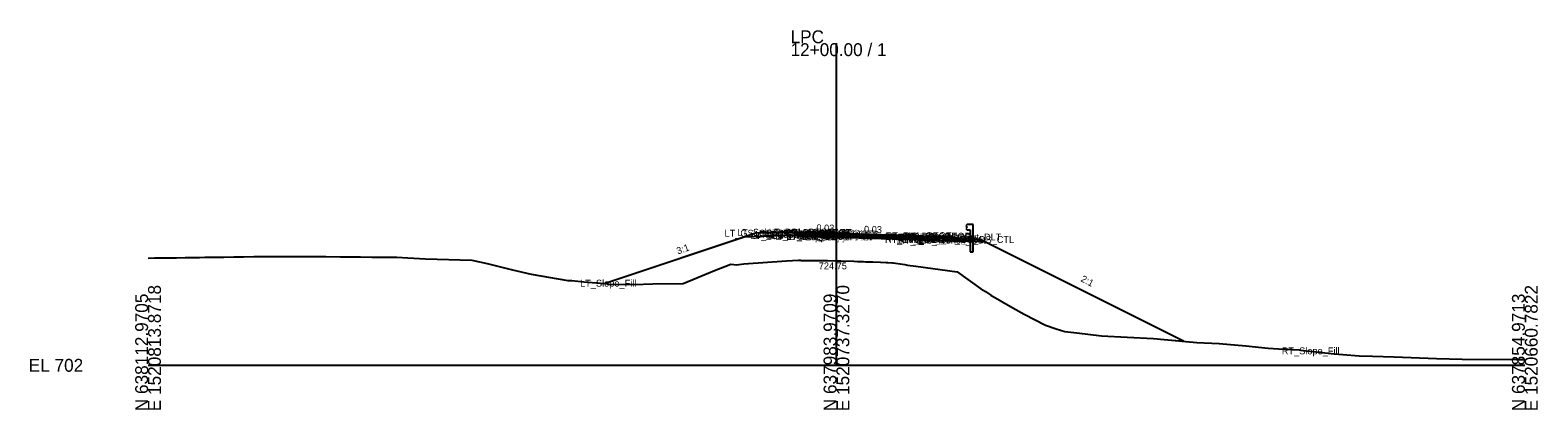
# Model space of a CAD drawing. Extents: x -26 to 303, y -10 to 4521.
# Drawn here: x -25.7 to 302.8, y 1990.3 to 2073 of the extents above; entities that cross this region are included whole.
import ezdxf

# ---------------------------------------------------------------- set-up
doc = ezdxf.new("R2010")
doc.units = 0
for name, color, linetype in [('Default', 7, 'Continuous'), ('Exist Cross Section Cell', 7, 'Continuous'), ('Exist XS Center Line Elevation Label', 7, 'Continuous'), ('Exist XS Ground Line', 7, 'Continuous'), ('Prop CMT Guardrail Graphics', 7, 'Continuous'), ('Prop CMT Pvmt Course 1', 7, 'Continuous'), ('Prop CMT Pvmt Course 2', 7, 'Continuous'), ('Prop CMT Pvmt Course 3', 7, 'Continuous'), ('Prop CMT Pvmt Surface', 7, 'Continuous'), ('Prop CMT Pvmt Surface Shoulder', 7, 'Continuous'), ('Prop CMT Shld Paved Course 1', 7, 'Continuous'), ('Prop CMT Shld Paved Course 2', 7, 'Continuous'), ('Prop CMT Shld Paved Course 3', 7, 'Continuous'), ('Prop CMT Slope Grass', 7, 'Continuous'), ('Prop CMT Subgrade Earthwork', 7, 'Continuous'), ('Prop XS Earthwork Shape', 7, 'Continuous'), ('Prop XS Shear Point Element', 7, 'Continuous')]:
    doc.layers.add(name, color=color, linetype=linetype)

msp = doc.modelspace()

# ---------------------------------------------------------------- linework, layer by layer
at = {"layer": 'Exist Cross Section Cell'}
for p, q in [((150, 2000), (150, 2070.13)), ((0, 2000), (150, 2000)), ((150, 2000), (300, 2000))]:
    msp.add_line(p, q, dxfattribs=at)
at = {"layer": 'Exist XS Ground Line'}
msp.add_lwpolyline([(0, 2023.35), (1.39, 2023.38), (2.09, 2023.39), (3.23, 2023.4), (3.45, 2023.4), (4.21, 2023.41), (5.39, 2023.42), (6.19, 2023.43), (8.08, 2023.46), (9.51, 2023.48), (10.2, 2023.48), (11.24, 2023.5), (12.37, 2023.52), (13.9, 2023.53), (14.95, 2023.55), (15.72, 2023.56), (16.17, 2023.57), (16.54, 2023.57), (18.69, 2023.6), (19.56, 2023.61), (20.81, 2023.63), (23.02, 2023.67), (24.96, 2023.66), (29.32, 2023.66), (30.49, 2023.68), (34.2, 2023.69), (35.79, 2023.68), (38.76, 2023.66), (41.93, 2023.64), (46.28, 2023.6), (48.79, 2023.58), (52.11, 2023.55), (53.38, 2023.54), (54.23, 2023.53), (56.62, 2023.4), (60.46, 2023.17), (70.54, 2022.89), (73.91, 2022.19), (79.44, 2020.82), (83.49, 2019.87), (91.47, 2018.45), (92.35, 2018.46), (94.97, 2018.21), (99.56, 2017.81), (100.45, 2017.67), (105.85, 2017.59), (110.02, 2017.75), (116.63, 2017.82), (123.45, 2020.63), (126.96, 2022.04), (127.62, 2021.92), (128.22, 2021.87), (129.84, 2022.07), (139.12, 2022.72), (141.7, 2022.86), (142.21, 2022.86), (142.26, 2022.85), (142.32, 2022.85), (142.55, 2022.85), (145.11, 2022.83), (145.44, 2022.84), (145.66, 2022.84), (146.76, 2022.82), (148.02, 2022.79), (150, 2022.75), (150.79, 2022.74), (150.91, 2022.74), (150.99, 2022.74), (153.81, 2022.65), (154.57, 2022.62), (155.88, 2022.58), (156.4, 2022.56), (156.72, 2022.55), (157.95, 2022.5), (159.62, 2022.44), (160.87, 2022.41), (161.17, 2022.41), (162.22, 2022.32), (162.33, 2022.31), (162.33, 2022.31), (162.35, 2022.31), (164.87, 2021.92), (165.49, 2021.82), (167.27, 2021.56), (176.3, 2020.33), (181.47, 2016.68), (182.49, 2016.07), (183.61, 2015.29), (188.46, 2012.54), (190.88, 2011.17), (195.58, 2008.71), (197.85, 2007.95), (199.77, 2007.37), (202.35, 2007.04), (207.73, 2006.43), (213.34, 2006.13), (219.08, 2005.84), (221.39, 2005.62), (228.52, 2004.98), (233.39, 2004.72), (239.21, 2004.22), (244.06, 2003.75), (246.34, 2003.61), (250.8, 2003.34), (251.15, 2003.32), (258.44, 2002.52), (260.38, 2002.36), (263.92, 2002.07), (266.79, 2001.98), (271.5, 2001.86), (280.76, 2001.51), (286.37, 2001.32), (298.18, 2001.29), (298.74, 2001.28), (298.83, 2001.28), (300, 2001.27)], dxfattribs=at)
at = {"layer": 'Prop CMT Guardrail Graphics'}
for points in [[(179.78, 2030.68), (178.45, 2030.68), (178.18, 2030.39)], [(178.18, 2030.39), (178.45, 2030.1)], [(179.78, 2024.68), (179.78, 2030.68)], [(178.45, 2030.1), (178.18, 2029.81)], [(178.18, 2029.81), (178.45, 2029.52), (179.12, 2029.52)], [(179.12, 2029.52), (179.12, 2024.68)], [(179.12, 2024.68), (179.78, 2024.68)]]:
    msp.add_lwpolyline(points, dxfattribs=at)
at = {"layer": 'Prop CMT Pvmt Course 1'}
msp.add_line((150.02, 2028.76), (167.01, 2028.23), dxfattribs=at)
for points in [[(150.02, 2028.76), (145.42, 2028.9)], [(145.42, 2028.9), (145.42, 2028.65)], [(145.42, 2028.65), (150.02, 2028.51)], [(150.02, 2028.51), (150.02, 2028.76)], [(150.02, 2028.51), (150.02, 2028.76)], [(167.01, 2027.98), (150.02, 2028.51)], [(167.01, 2028.23), (167.01, 2027.98)]]:
    msp.add_lwpolyline(points, dxfattribs=at)
msp.add_lwpolyline([(150.02, 2028.51), (150.02, 2028.63), (150.02, 2028.63), (150.02, 2028.51)], close=True, dxfattribs=at)
msp.add_lwpolyline([(150.02, 2028.51), (150.02, 2028.63), (150.02, 2028.63), (150.02, 2028.51)], close=True, dxfattribs=at)
at = {"layer": 'Prop CMT Pvmt Course 2'}
for points in [[(150.02, 2028.51), (145.42, 2028.65)], [(145.42, 2028.65), (145.42, 2028.32)], [(145.42, 2028.32), (150.02, 2028.18)], [(150.02, 2028.18), (150.02, 2028.51)], [(150.02, 2028.18), (150.02, 2028.51)], [(150.02, 2028.51), (167.01, 2027.98)], [(167.01, 2027.65), (150.02, 2028.18)], [(167.01, 2027.98), (167.01, 2027.65)]]:
    msp.add_lwpolyline(points, dxfattribs=at)
at = {"layer": 'Prop CMT Pvmt Course 3'}
for points in [[(150.02, 2028.18), (145.42, 2028.32)], [(145.42, 2028.32), (145.42, 2028.07)], [(145.42, 2028.07), (150.02, 2027.93)], [(150.02, 2027.93), (150.02, 2028.18)], [(150.02, 2028.18), (167.01, 2027.65)], [(150.02, 2027.93), (150.02, 2028.18)], [(167.01, 2027.4), (150.02, 2027.93)], [(167.01, 2027.65), (167.01, 2027.4)]]:
    msp.add_lwpolyline(points, dxfattribs=at)
at = {"layer": 'Prop CMT Pvmt Surface'}
for points in [[(150.02, 2028.76), (145.42, 2028.9)], [(150.02, 2028.76), (167.01, 2028.23)]]:
    msp.add_lwpolyline(points, dxfattribs=at)
at = {"layer": 'Prop CMT Pvmt Surface Shoulder'}
for points in [[(145.42, 2028.9), (141.42, 2029.02)], [(167.01, 2028.23), (171.01, 2028.11)]]:
    msp.add_lwpolyline(points, dxfattribs=at)
at = {"layer": 'Prop CMT Shld Paved Course 1'}
for p in [(171.28, 2027.84), (178.18, 2027.65)]:
    msp.add_line(p, (178.18, 2027.39), dxfattribs=at)
for points in [[(145.42, 2028.9), (141.42, 2029.02), (141.17, 2028.78)], [(141.17, 2028.78), (145.42, 2028.65)], [(145.42, 2028.65), (145.42, 2028.9)], [(167.01, 2028.23), (171.01, 2028.11), (171.27, 2027.85)], [(167.01, 2027.98), (167.01, 2028.23)], [(171.27, 2027.85), (167.01, 2027.98)]]:
    msp.add_lwpolyline(points, dxfattribs=at)
at = {"layer": 'Prop CMT Shld Paved Course 2'}
for points in [[(145.42, 2028.65), (141.17, 2028.78), (140.85, 2028.46)], [(140.85, 2028.46), (145.42, 2028.32)], [(145.42, 2028.32), (145.42, 2028.65)], [(167.01, 2027.98), (171.27, 2027.85), (171.61, 2027.51)], [(167.01, 2027.65), (167.01, 2027.98)], [(171.61, 2027.51), (167.01, 2027.65)]]:
    msp.add_lwpolyline(points, dxfattribs=at)
at = {"layer": 'Prop CMT Shld Paved Course 3'}
for p, q in [((140.85, 2028.46), (140.61, 2028.22)), ((171.61, 2027.51), (171.87, 2027.25))]:
    msp.add_line(p, q, dxfattribs=at)
for points in [[(140.11, 2028.23), (145.42, 2028.07)], [(145.42, 2028.32), (140.85, 2028.46), (140.61, 2028.22)], [(145.42, 2028.07), (145.42, 2028.32)], [(167.01, 2027.4), (167.01, 2027.65)], [(167.01, 2027.65), (171.61, 2027.51), (171.87, 2027.25)], [(172.37, 2027.24), (167.01, 2027.4)]]:
    msp.add_lwpolyline(points, dxfattribs=at)
at = {"layer": 'Prop CMT Slope Grass'}
msp.add_line((225.6, 2005.24), (181.18, 2027.45), dxfattribs=at)
for points in [[(141.42, 2029.02), (132.42, 2028.76), (99.57, 2017.81)], [(171.01, 2028.11), (181.18, 2027.45)]]:
    msp.add_lwpolyline(points, dxfattribs=at)
at = {"layer": 'Prop CMT Subgrade Earthwork'}
for points in [[(140.11, 2028.23), (129.89, 2027.92)], [(145.42, 2028.07), (140.11, 2028.23)], [(150.02, 2027.93), (145.42, 2028.07)], [(150.02, 2027.93), (167.01, 2027.4)], [(167.01, 2027.4), (182.22, 2026.93)]]:
    msp.add_lwpolyline(points, dxfattribs=at)
at = {"layer": 'Prop XS Earthwork Shape'}
msp.add_lwpolyline([(150.02, 2027.93), (145.42, 2028.07), (140.11, 2028.23), (129.89, 2027.92), (99.57, 2017.81), (100.45, 2017.67), (105.85, 2017.59), (110.02, 2017.75), (116.63, 2017.82), (123.45, 2020.63), (126.96, 2022.04), (127.62, 2021.92), (128.22, 2021.87), (129.84, 2022.07), (139.12, 2022.72), (141.7, 2022.86), (142.21, 2022.86), (142.32, 2022.85), (142.55, 2022.85), (145.11, 2022.83), (145.44, 2022.84), (145.66, 2022.84), (146.76, 2022.82), (148.02, 2022.79), (150, 2022.75), (150.79, 2022.74), (150.99, 2022.74), (153.81, 2022.65), (154.57, 2022.62), (155.88, 2022.58), (156.4, 2022.56), (156.72, 2022.55), (157.95, 2022.5), (159.62, 2022.44), (160.87, 2022.41), (161.17, 2022.41), (162.22, 2022.32), (162.35, 2022.31), (164.87, 2021.92), (165.49, 2021.82), (167.27, 2021.56), (176.3, 2020.33), (181.47, 2016.68), (182.49, 2016.07), (183.61, 2015.29), (188.46, 2012.54), (190.88, 2011.17), (195.58, 2008.71), (197.85, 2007.95), (199.77, 2007.37), (202.35, 2007.04), (207.73, 2006.43), (213.34, 2006.13), (219.08, 2005.84), (221.39, 2005.62), (225.6, 2005.24), (182.22, 2026.93), (167.01, 2027.4)], close=True, dxfattribs=at)

# ---------------------------------------------------------------- texts
at = {"layer": 'Default'}
msp.add_text('-', height=0.0001, dxfattribs=at).set_placement((0, 2000))
at = {"layer": 'Exist Cross Section Cell'}
for s, p in [('12+00.00 / 1', (140, 2067.33)), ('LPC', (140, 2070.13)), ('EL 702', (-26, 1998.6))]:
    msp.add_text(s, height=2.8, dxfattribs=at).set_placement(p)
for s, p in [('E 1520813.8718', (2.8, 1990)), ('E 1520737.3270', (152.8, 1990)), ('E 1520660.7822', (302.8, 1990)), ('N 638112.9705', (0, 1990)), ('N 637983.9709', (150, 1990)), ('N 637854.9713', (300, 1990))]:
    msp.add_text(s, height=2.8, rotation=90, dxfattribs=at).set_placement(p)
at = {"layer": 'Exist XS Center Line Elevation Label'}
for s, rotation, p in [('0.03', 358.8358, (145.62, 2029.19)), ('0.03', 358.8358, (156, 2028.87)), ('3:1', 19.8357, (115.46, 2024.12)), ('2:1', 332.3479, (203.11, 2018.35))]:
    msp.add_text(s, height=1.5, rotation=rotation, dxfattribs=at).set_placement(p)
msp.add_text('724.75', height=1.5, dxfattribs=at).set_placement((146.14, 2020.9))
at = {"layer": 'Prop XS Shear Point Element'}
for s, p in [('LT_GS_OS_CTL', (125.61, 2028.01)), ('LT_Sub_Trench_Out_DLT', (128.36, 2028.21)), ('LT_Sub_Trench_Out', (131.28, 2027.48)), ('LT_PS3_Shelf_Out', (132.34, 2027.72)), ('LT_PS3_OEOP', (134.53, 2027.71)), ('LT_PS2_OEOP', (134.85, 2028.03)), ('LT_PS1_OEOP', (135.28, 2028.27)), ('LT_PV2_OEOT', (139.03, 2027.9)), ('LT_PV3_OEOT', (139.03, 2027.57)), ('LT_Sub_OEOT', (139.07, 2027.32)), ('LT_PV1_OEOT', (139.21, 2028.15)), ('RT_PV2_OEEOP', (143.02, 2027.76)), ('RT_PV3_OEEOP', (143.02, 2027.43)), ('RT_Sub_OEEOP', (143.05, 2027.18)), ('LT_PV2_OEEOP', (143.1, 2027.76)), ('LT_PV3_OEEOP', (143.1, 2027.43)), ('LT_Sub_OEEOP', (143.14, 2027.18)), ('RT_PV1_OEEOP', (143.2, 2027.88)), ('LT_PV1_OEEOP', (143.28, 2027.88)), ('RT_PV2_IEEOP', (143.59, 2027.76)), ('LT_PV2_IEEOP', (143.67, 2027.76)), ('RT_PV1_IEEOP', (143.77, 2027.88)), ('LT_PV1_IEEOP', (143.85, 2027.88)), ('PV2_PGL', (146.04, 2027.76)), ('PV1_PGL', (146.22, 2028.01)), ('RT_PV2_OEOT', (160.54, 2027.23)), ('RT_PV3_OEOT', (160.54, 2026.9)), ('RT_Sub_OEOT', (160.58, 2026.65)), ('RT_PV1_OEOT', (160.72, 2027.48)), ('RT_Sub_Trench_Out_DLT', (161.96, 2027.19)), ('RT_Sub_Trench_Out', (163.44, 2026.49)), ('RT_PS3_Shelf_Out', (164.01, 2026.74)), ('RT_PS1_OEOP', (164.78, 2027.36)), ('RT_PS2_OEOP', (164.86, 2027.1)), ('RT_PS3_OEOP', (165.2, 2026.76)), ('RT_GS_OS_CTL', (173.12, 2026.64)), ('LT_Slope_Fill', (94.14, 2017.13)), ('RT_Slope_Fill', (247.04, 2002.39))]:
    msp.add_text(s, height=1.5, dxfattribs=at).set_placement(p)

doc.saveas('drawing.dxf')
